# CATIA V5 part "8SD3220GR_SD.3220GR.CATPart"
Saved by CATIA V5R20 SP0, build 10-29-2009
Part number: 8SD3220GR_SD.3220GR
Revision: ANY
Definition: UNKNOWN
Nomenclature: 8SD3220GR_SD.3220GR
Source: Unknown
Bounding box of the stored display mesh (mm): x -16 to 16, y -18.5 to 18.5, z -10 to 10
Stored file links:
  C:\Users\Utente\Desktop\IO LAVORO\3D X SITO CF\CUMSA\3D files SD\SD 3220\8SD3220GR_SD.3220GR.CATPart
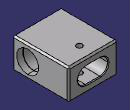
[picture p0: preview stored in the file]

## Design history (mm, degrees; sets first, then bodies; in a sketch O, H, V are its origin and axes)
Body1 "Chaflán3" (main body)
  Solid1: solid without history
